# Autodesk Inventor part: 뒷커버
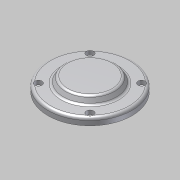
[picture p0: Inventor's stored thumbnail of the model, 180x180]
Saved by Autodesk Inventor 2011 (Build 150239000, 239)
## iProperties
Created: 2013-02
Part Number: 뒷커버
Document SubType Name: Modeling
Designer: 한국산업디자인학원[gmhk.co.kr]
Density: 1 g/cm^3
Author: 한국산업디자인학원[gmhk.co.kr]
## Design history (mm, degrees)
sketch "스케치1"
  geometry: C1 r 30 at (0, 0) reference; C2 r 46 at (0, 0); A1 r 91.05 centre (0, -48.55) between (34.185, 35.839) and (-34.185, 35.839) reference; A2 r 91.05 centre (48.55, 0) between (-35.839, 34.185) and (-35.839, -34.185) reference; A3 r 3 centre (-33.058, 33.058) between (-34.185, 35.839) and (-35.839, 34.185) reference; A4 r 3 centre (33.058, 33.058) between (35.839, 34.185) and (34.185, 35.839) reference; A5 r 91.05 centre (-48.55, 0) between (35.839, -34.185) and (35.839, 34.185) reference; A6 r 3 centre (33.058, -33.058) between (34.185, -35.839) and (35.839, -34.185) reference; A7 r 91.05 centre (0, 48.55) between (-34.185, -35.839) and (34.185, -35.839) reference; A8 r 3 centre (-33.058, -33.058) between (-35.839, -34.185) and (-34.185, -35.839) reference; 1 further point
  constraints: 1 centre point, 1 coincident
  dimensions: "d37" = 92 diameter of C2
  node "참조1"
  node "참조2"
  node "참조3"
  node "참조4"
  node "참조5"
  node "참조6"
  node "참조7"
  node "참조8"
  node "참조9"
extrude "돌출1" new body sketch "스케치1" distance "d0" = 8; taper "d1" = 0 deg
sketch "스케치2"
  geometry: C1 r 30 at (0, 0); 1 further point
  constraints: 1 centre point, 1 coincident
  dimensions: "d2" = 60 diameter of C1
extrude "돌출2" join sketch "스케치2" distance "d3" = 7; taper "d4" = -30 deg
sketch "스케치3"
  geometry: C1 r 1.621 at (28.284, 28.284) reference; C2 r 1.621 at (-28.284, 28.284) reference; C3 r 1.621 at (-28.284, -28.284) reference; C4 r 1.621 at (28.284, -28.284) reference; 1 further point
hole "구멍2" sketch "스케치3" at (28.284, 28.284), (28.284, -28.284), (-28.284, -28.284), (-28.284, 28.284) diameter "d14" = 4.5; stored, may be unused: countersink angle "d18" = 90 deg, drill point angle "d20" = 118 deg; dims "d15" = 6, "d16" = 8, "d17" = 4.4, "d19" = 20
extrude "돌출3" join sketch "스케치1" distance "d21" = 12; taper "d22" = 0 deg
hole "구멍3" diameter "d25" = 30; stored, may be unused: countersink angle "d29" = 90 deg, drill point angle "d31" = 0 deg; dims "d23" = 10, "d24" = 10, "d26" = 6, "d27" = 40, "d28" = 12, "d30" = 15
fillet "모깎기1" dims "d32" = 3, "d33" = 0.3
chamfer "모따기1" distance "d34" = 1; stored, may be unused: second distance "d35" = 2, angle "d36" = 45 deg
fillet "모깎기2" dims "d38" = 3
node "솔리드1"
node "참조10"
node "참조11"
node "참조12"
node "참조13"
